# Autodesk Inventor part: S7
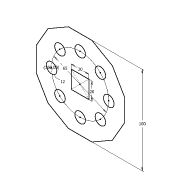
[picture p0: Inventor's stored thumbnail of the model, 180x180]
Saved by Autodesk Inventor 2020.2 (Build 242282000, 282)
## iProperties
Created: 2013-12
Part Number: S7
Material: Ogólny
Document SubType Name: Modeling
Designer: F.Stasiak
Density: 1 g/cm^3
Appearance: Domyślna
Manager: www.cadconsulting.pl
Company: Fabian Stasiak CAD Consulting
Author: F.Stasiak
Subject: Zbiór ćwiczeń. Autodesk Inventor 2020. Kurs podstawowy
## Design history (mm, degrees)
sketch "Szkic1" dims "d2" = 65
  geometry: L1 (-10, -10)-(10, -10); L2 (10, -10)-(10, 10); L3 (10, 10)-(-10, 10); L4 (-10, 10)-(-10, -10); L5 (-10, -10)-(10, 10); L6 (10, -10)-(-10, 10); L7 (-50, 13.397)-(-36.603, 36.603); L8 (-36.603, 36.603)-(-13.397, 50); L9 (-13.397, 50)-(13.397, 50); L10 (13.397, 50)-(36.603, 36.603); L11 (36.603, 36.603)-(50, 13.397); L12 (50, 13.397)-(50, -13.397); L13 (50, -13.397)-(36.603, -36.603); L14 (36.603, -36.603)-(13.397, -50); L15 (13.397, -50)-(-13.397, -50); L16 (-13.397, -50)-(-36.603, -36.603); L17 (-36.603, -36.603)-(-50, -13.397); L18 (-50, -13.397)-(-50, 13.397); C1 r 6 at (-32.5, 0); C2 r 6 at (-22.981, -22.981); C3 r 6 at (0, -32.5); C4 r 6 at (22.981, -22.981); C5 r 6 at (32.5, 0); C6 r 6 at (22.981, 22.981); C7 r 6 at (0, 32.5); C8 r 6 at (-22.981, 22.981); 4 further points
  constraints: 36 end point, 8 centre point, 3 midpoint, 2 coincident, 2 collinear, 2 horizontal alignment, 1 horizontal, 1 perpendicular, 1 vertical, 44 other
  dimensions: "d0" = 20 distance of L3.end L2.end; "d1" = 20 distance of L2.end L1.end; "d3" = 12 diameter of C1; "d4" = 100 distance between parallel lines of L9 L15; "d7" = 360 deg dimension on point (0, 0) C1.centre (derived)
